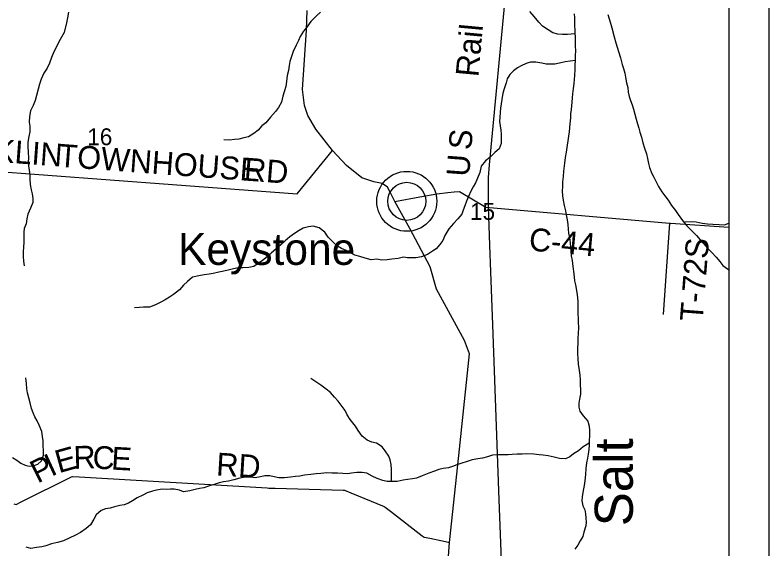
# Model space of a CAD drawing. Extents: x 0 to 34, y 0 to 22.
# Drawn here: x 7.127 to 9, y 16.276 to 17.601 of the extents above; entities that cross this region are included whole.
import ezdxf

# ---------------------------------------------------------------- set-up
doc = ezdxf.new("R2010")
doc.units = 0
for name, color, linetype in [('GM_X_County_Road', 7, 'Continuous'), ('GM_X_County_Road_Text', 7, 'Continuous'), ('GM_X_Major_River', 7, 'Continuous'), ('GM_X_Major_River_Text', 7, 'Continuous'), ('GM_X_Minor_River', 7, 'Continuous'), ('GM_X_Rail_Line', 7, 'Continuous'), ('GM_X_Rail_Line_Text', 7, 'Continuous'), ('GM_X_Section_Text', 7, 'Continuous'), ('GM_X_Township_Road', 7, 'Continuous'), ('GM_X_Township_Road_Text', 7, 'Continuous'), ('GM_X_Unincorporated', 7, 'Continuous'), ('GM_X_Unincorporated_Location', 7, 'Continuous'), ('GM_X_Unincorporated_Text', 7, 'Continuous'), ('SH_Data', 7, 'Continuous')]:
    doc.layers.add(name, color=color, linetype=linetype)

msp = doc.modelspace()

# ---------------------------------------------------------------- linework, layer by layer
at = {"layer": 'GM_X_County_Road'}
for points in [[(8.1931, 16.1084), (8.2061, 16.2922), (8.2296, 16.5078), (8.2558, 16.7601), (8.2439, 16.7934), (8.1745, 16.9209), (8.158, 16.9765), (8.108, 17.0711), (8.0705, 17.1387), (8.06, 17.1604), (8.0524, 17.174), (8.0395, 17.183), (8.0186, 17.1875), (7.9883, 17.1976), (7.9504, 17.2281), (7.9156, 17.2654), (7.8747, 17.318), (7.8541, 17.3516), (7.8465, 17.377), (7.841, 17.4164), (7.851, 17.564), (7.8526, 17.6125)], [(8.0705, 17.1387), (8.1327, 17.1497), (8.1746, 17.1571), (8.2019, 17.1607), (8.2181, 17.1623), (8.231, 17.1635), (8.2966, 17.1243), (8.7534, 17.085), (8.7553, 17.0848), (8.9, 17.0747)]]:
    msp.add_lwpolyline(points, dxfattribs=at)
at = {"layer": 'GM_X_Major_River'}
for points in [[(8.5163, 17.6046), (8.5166, 17.5948), (8.5172, 17.58), (8.5178, 17.5587), (8.5184, 17.5451), (8.5187, 17.5345), (8.519, 17.5246), (8.5192, 17.5121), (8.5188, 17.5015), (8.5183, 17.4897), (8.5182, 17.4768), (8.5177, 17.4662), (8.5168, 17.4515), (8.5151, 17.4318), (8.5135, 17.4189), (8.5123, 17.4056), (8.5114, 17.3962), (8.5102, 17.3852), (8.5085, 17.367), (8.5073, 17.3564), (8.5068, 17.3458), (8.5052, 17.3314), (8.5043, 17.3219), (8.5035, 17.3117), (8.5023, 17.3007), (8.5007, 17.289), (8.4991, 17.2787), (8.4959, 17.2606), (8.4942, 17.2481), (8.4919, 17.2337), (8.4898, 17.2136), (8.4885, 17.2007), (8.4873, 17.1871), (8.4868, 17.1753), (8.4863, 17.1647), (8.487, 17.1526), (8.4888, 17.1416), (8.4917, 17.1283), (8.4946, 17.1154), (8.4964, 17.1051), (8.4986, 17.093), (8.5007, 17.0816), (8.5014, 17.0702), (8.502, 17.0599), (8.5042, 17.0489), (8.506, 17.0356), (8.507, 17.0246), (8.5077, 17.0152), (8.5091, 17.0038), (8.5109, 16.9916), (8.513, 16.9768), (8.5151, 16.9586), (8.5173, 16.9419), (8.5191, 16.9316), (8.5212, 16.9221), (8.5234, 16.907), (8.5251, 16.891), (8.5254, 16.8804), (8.5253, 16.8705), (8.5256, 16.8588), (8.5259, 16.8485), (8.5262, 16.8387), (8.5268, 16.8254), (8.5263, 16.8106), (8.5251, 16.7993), (8.525, 16.7871), (8.5245, 16.7743), (8.5247, 16.7606), (8.525, 16.7488), (8.5264, 16.7344), (8.5285, 16.7189), (8.5299, 16.7075), (8.531, 16.6957)], [(8.531, 16.6957), (8.5312, 16.6832), (8.5319, 16.6707), (8.5318, 16.6601), (8.5298, 16.648), (8.5278, 16.6381), (8.5277, 16.6279), (8.5303, 16.618), (8.5385, 16.6065), (8.5501, 16.5928), (8.5538, 16.5806), (8.554, 16.57), (8.5543, 16.5575), (8.5538, 16.5439), (8.5533, 16.5332), (8.5525, 16.523), (8.5509, 16.5113), (8.5493, 16.501), (8.5469, 16.4897), (8.5453, 16.4757), (8.544, 16.4609), (8.5424, 16.4446), (8.5407, 16.4336), (8.5387, 16.4208), (8.5363, 16.4049), (8.5355, 16.395), (8.538, 16.3825), (8.5425, 16.3726), (8.5447, 16.3631), (8.5453, 16.3525), (8.5456, 16.3426), (8.5452, 16.3331), (8.5405, 16.3176), (8.5374, 16.307), (8.5308, 16.2957), (8.5255, 16.2852), (8.5174, 16.2754)]]:
    msp.add_lwpolyline(points, dxfattribs=at)
at = {"layer": 'GM_X_Minor_River'}
for points in [[(7.26, 17.6085), (7.2576, 17.5948), (7.2549, 17.5819), (7.249, 17.5583)], [(7.8862, 17.6083), (7.8764, 17.5992), (7.8623, 17.5853), (7.8517, 17.5713), (7.8441, 17.5614), (7.8357, 17.5478), (7.8311, 17.538), (7.8258, 17.527), (7.8181, 17.5108), (7.8128, 17.496), (7.8101, 17.4862), (7.8085, 17.4763), (7.8062, 17.4634), (7.8035, 17.4509), (7.8016, 17.4362), (7.7996, 17.424), (7.7958, 17.4108), (7.7927, 17.3998), (7.7889, 17.3854), (7.782, 17.3722), (7.774, 17.3616), (7.7619, 17.3476), (7.7501, 17.334), (7.7406, 17.3265), (7.7308, 17.3156), (7.7201, 17.3076), (7.7072, 17.299), (7.6959, 17.2968), (7.683, 17.293), (7.6725, 17.2927), (7.6596, 17.2905), (7.646, 17.2913)], [(8.5179, 17.5549), (8.4998, 17.5528), (8.4869, 17.5532), (8.4756, 17.5536), (8.4628, 17.5571), (8.4518, 17.5644), (8.4375, 17.5735), (8.4281, 17.5838), (8.4168, 17.5975), (8.4063, 17.6101)], [(8.6002, 17.6031), (8.6027, 17.5921), (8.6061, 17.5815), (8.6095, 17.5697), (8.6154, 17.5469), (8.6199, 17.5325), (8.6232, 17.5215), (8.6262, 17.5109), (8.6311, 17.4953), (8.6351, 17.4786), (8.6385, 17.4688), (8.6418, 17.457), (8.6433, 17.4475), (8.6463, 17.4335), (8.6493, 17.4213), (8.6507, 17.4103), (8.6529, 17.3993), (8.6563, 17.3891), (8.6604, 17.3781), (8.6638, 17.3678), (8.6667, 17.3553), (8.6705, 17.3428), (8.6734, 17.3314), (8.6768, 17.3204), (8.6794, 17.3109), (8.6835, 17.298), (8.6865, 17.2843), (8.6913, 17.2706), (8.6958, 17.2566), (8.698, 17.2456), (8.7006, 17.2327), (8.7036, 17.2232), (8.7088, 17.208), (8.7137, 17.1985), (8.7208, 17.1856), (8.7257, 17.1757), (8.7339, 17.1628), (8.7411, 17.1529), (8.7493, 17.1415), (8.7576, 17.1285), (8.7677, 17.116), (8.7749, 17.1061), (8.785, 17.0913), (8.7963, 17.078), (8.8095, 17.065), (8.82, 17.0543), (8.829, 17.0437), (8.8384, 17.033), (8.8475, 17.0228), (8.858, 17.0117), (8.8689, 16.9999), (8.8779, 16.9896), (8.8858, 16.9797), (8.8971, 16.971), (8.9, 16.9679)], [(7.249, 17.5583), (7.2358, 17.5349), (7.2305, 17.5228), (7.2236, 17.5099), (7.2175, 17.4963), (7.2129, 17.4819), (7.2068, 17.4698), (7.1988, 17.4569), (7.1916, 17.4425), (7.1878, 17.4297), (7.1847, 17.4176), (7.1801, 17.4013), (7.1774, 17.3895), (7.1721, 17.377), (7.1656, 17.3634), (7.1629, 17.3494), (7.1621, 17.3358), (7.1635, 17.3255), (7.1635, 17.3111), (7.1616, 17.3001), (7.1589, 17.2861), (7.1592, 17.2755), (7.1595, 17.2603), (7.1602, 17.2467), (7.1598, 17.2365), (7.1605, 17.227), (7.162, 17.2164), (7.1635, 17.2038), (7.1642, 17.1944), (7.1649, 17.1807), (7.1671, 17.1674), (7.1694, 17.1579), (7.1712, 17.1458), (7.1712, 17.1363), (7.1654, 17.1216), (7.159, 17.1072), (7.1566, 17.0951), (7.1551, 17.0833), (7.1494, 17.0716), (7.1486, 17.0621), (7.1493, 17.0481), (7.1492, 17.0386), (7.1481, 17.0246), (7.1473, 17.0144), (7.1476, 17.0019), (7.1483, 16.9905), (7.1494, 16.9787)], [(8.5183, 17.4886), (8.4938, 17.485), (8.4794, 17.482), (8.4681, 17.4794), (8.4567, 17.4791), (8.4469, 17.4795), (8.436, 17.4818), (8.4209, 17.4845), (8.4073, 17.4846), (8.397, 17.4808), (8.3849, 17.4752), (8.3751, 17.4703), (8.3652, 17.4632), (8.3561, 17.4534), (8.35, 17.4431), (8.3469, 17.4333), (8.342, 17.4182), (8.3393, 17.4076), (8.3362, 17.3917), (8.3346, 17.381), (8.3334, 17.3701), (8.331, 17.3371), (8.3325, 17.3265), (8.3336, 17.3159), (8.3347, 17.306), (8.335, 17.2927), (8.335, 17.2821), (8.33, 17.2689), (8.3194, 17.2602), (8.3068, 17.2474), (8.2955, 17.2394), (8.2848, 17.2262), (8.2814, 17.2103), (8.2764, 17.1963), (8.271, 17.1846), (8.2649, 17.1748), (8.2592, 17.1642), (8.2539, 17.1509), (8.2489, 17.1392), (8.2443, 17.1278), (8.2401, 17.1173), (8.2367, 17.1074), (8.2272, 17.0953), (8.2166, 17.084), (8.2044, 17.0708), (8.1949, 17.0542), (8.1899, 17.042), (8.1823, 17.0318), (8.1736, 17.0213), (8.1641, 17.0149), (8.152, 17.007), (8.1368, 17.001), (8.1232, 16.9984), (8.1126, 16.9984), (8.102, 16.9988), (8.0922, 17), (8.0786, 16.9971), (8.0631, 16.9952), (8.0514, 16.9934), (8.0385, 16.9931), (8.0257, 16.9954), (8.0117, 16.9936), (7.9966, 16.9978), (7.9838, 17.0017), (7.9713, 17.0051), (7.9604, 17.0112), (7.9498, 17.0166), (7.9381, 17.022), (7.9283, 17.0277), (7.9163, 17.0384), (7.9046, 17.0498), (7.8967, 17.062), (7.8824, 17.073), (7.8681, 17.0772), (7.856, 17.0754), (7.8431, 17.0721), (7.8332, 17.0664), (7.8215, 17.0589), (7.8101, 17.051), (7.798, 17.0408), (7.787, 17.031), (7.7756, 17.0212), (7.7631, 17.0102), (7.7532, 17.0012), (7.7418, 16.9921), (7.7308, 16.9846), (7.7206, 16.9775), (7.7081, 16.9749), (7.6926, 16.9742), (7.6813, 16.9738), (7.6695, 16.9709), (7.6567, 16.9679), (7.6457, 16.9653), (7.6332, 16.9631), (7.6196, 16.9597), (7.6094, 16.9579), (7.5969, 16.9564), (7.5841, 16.9542), (7.5678, 16.9505), (7.5556, 16.9399), (7.5458, 16.9305)], [(8.7877, 17.0881), (8.8092, 17.0889), (8.8194, 17.0881), (8.8341, 17.085), (8.8473, 17.083), (8.861, 17.0826), (8.8761, 17.0814), (8.8897, 17.0802), (8.9, 17.0847)], [(7.5458, 16.9305), (7.5355, 16.9192), (7.5204, 16.9079), (7.5105, 16.9007), (7.4999, 16.8943), (7.4893, 16.8887), (7.4764, 16.8823), (7.4609, 16.8763), (7.4461, 16.8764), (7.4363, 16.8753), (7.4235, 16.8742)], [(7.1208, 16.5027), (7.1314, 16.4959), (7.1415, 16.489), (7.1521, 16.4836), (7.1619, 16.4817), (7.1722, 16.4821), (7.1835, 16.4866), (7.193, 16.4945), (7.198, 16.5085), (7.1976, 16.518), (7.1973, 16.5343), (7.197, 16.5445), (7.1955, 16.5551), (7.1937, 16.5673), (7.1869, 16.5832), (7.182, 16.5942), (7.1764, 16.6041), (7.1719, 16.614), (7.1681, 16.6242), (7.1648, 16.6383), (7.1614, 16.6512), (7.1581, 16.6637), (7.1562, 16.6735), (7.1555, 16.6864), (7.154, 16.7008)], [(8.0621, 16.4434), (8.0623, 16.4607), (8.0624, 16.4732), (8.0616, 16.4854), (8.0594, 16.4968), (8.0557, 16.5062), (8.0467, 16.5196), (8.0388, 16.5291), (8.0252, 16.5382), (8.0131, 16.5409), (8.0018, 16.5459), (7.9894, 16.5562), (7.9792, 16.5703), (7.9729, 16.5805), (7.9593, 16.5969), (7.9522, 16.6091), (7.9473, 16.6193), (7.9372, 16.633), (7.9297, 16.6425), (7.9206, 16.6524), (7.9105, 16.6642), (7.9003, 16.6726), (7.8868, 16.6825), (7.8743, 16.6905), (7.8619, 16.6989)], [(8.5536, 16.5387), (8.5384, 16.5295), (8.5267, 16.5197), (8.5146, 16.5121), (8.5051, 16.5042), (8.4948, 16.4993), (8.4794, 16.5005), (8.4665, 16.504), (8.4518, 16.5067), (8.4393, 16.5087), (8.4295, 16.5095), (8.4159, 16.5114), (8.3989, 16.5119), (8.3868, 16.5108), (8.3743, 16.5112), (8.3622, 16.5102), (8.3524, 16.5098), (8.3278, 16.5099), (8.3135, 16.5089), (8.301, 16.5044), (8.2881, 16.501), (8.2771, 16.4999), (8.2631, 16.4973), (8.2476, 16.4925), (8.2374, 16.4891), (8.2245, 16.485), (8.2139, 16.4805), (8.2037, 16.4775), (8.1905, 16.4757), (8.1799, 16.4731), (8.1689, 16.4693), (8.1549, 16.4637), (8.1386, 16.457), (8.1246, 16.4513), (8.1148, 16.4499), (8.1023, 16.4484), (8.0913, 16.447), (8.0766, 16.4432), (8.0668, 16.4433), (8.0516, 16.4437), (8.0411, 16.4457), (8.0267, 16.451), (8.0143, 16.4568), (8.0007, 16.4637), (7.9894, 16.4656), (7.9765, 16.466), (7.9629, 16.4638), (7.9531, 16.4627), (7.9414, 16.4632), (7.9285, 16.4636), (7.9145, 16.4644), (7.9013, 16.4649), (7.8866, 16.4634), (7.8752, 16.4623), (7.862, 16.4609), (7.8465, 16.4591), (7.8348, 16.4568), (7.8238, 16.4557), (7.8117, 16.4539), (7.7969, 16.4528), (7.7822, 16.4525), (7.7705, 16.4552), (7.7603, 16.4572), (7.7475, 16.4576), (7.7372, 16.455), (7.7236, 16.4528), (7.7115, 16.454), (7.6987, 16.4537), (7.6854, 16.4514), (7.6707, 16.4473), (7.6578, 16.4444), (7.6446, 16.4422), (7.634, 16.4403), (7.6242, 16.4369), (7.6101, 16.4328), (7.5958, 16.428), (7.5856, 16.4257), (7.575, 16.4235), (7.561, 16.4202), (7.5455, 16.418), (7.5356, 16.4222), (7.5228, 16.4241), (7.513, 16.4246), (7.5024, 16.4238), (7.4922, 16.4239), (7.4786, 16.4217), (7.4684, 16.4195), (7.4555, 16.415), (7.4449, 16.4097), (7.4301, 16.4026), (7.4187, 16.3954), (7.4089, 16.3898), (7.3979, 16.3857), (7.3873, 16.3834), (7.3741, 16.3805), (7.3631, 16.3771), (7.3521, 16.3756), (7.3408, 16.3715), (7.3286, 16.3606), (7.3225, 16.3496), (7.3146, 16.336)], [(7.3146, 16.336), (7.3039, 16.3269), (7.2899, 16.3168), (7.277, 16.31), (7.2472, 16.2956)], [(7.2472, 16.2956), (7.2327, 16.2915), (7.218, 16.2882), (7.204, 16.2833), (7.1934, 16.2814), (7.1805, 16.2792), (7.1665, 16.277), (7.1548, 16.2805)]]:
    msp.add_lwpolyline(points, dxfattribs=at)
at = {"layer": 'GM_X_Rail_Line'}
msp.add_lwpolyline([(8.336, 16.2482), (8.3302, 16.398), (8.3141, 16.8322), (8.3089, 16.9635), (8.3066, 17.0299), (8.3031, 17.1252), (8.3035, 17.1977), (8.3057, 17.2297), (8.3479, 17.6756), (8.359, 17.7858), (8.3651, 17.8594), (8.3677, 17.925), (8.3681, 17.9495), (8.3622, 18.0352), (8.3594, 18.06), (8.3556, 18.089), (8.3502, 18.1187), (8.3464, 18.1394), (8.3312, 18.2048), (8.3106, 18.2737), (8.2615, 18.4057), (8.1892, 18.5986), (8.0513, 18.9649)], dxfattribs=at)
at = {"layer": 'GM_X_Township_Road'}
msp.add_line((8.7534, 17.085), (8.7373, 16.8583), dxfattribs=at)
for points in [[(6.5886, 17.2499), (7.8282, 17.1576), (7.9156, 17.2654)], [(7.1241, 16.3881), (7.1299, 16.3865), (7.1424, 16.3927), (7.2671, 16.4546), (7.2699, 16.456), (7.2867, 16.455), (7.7536, 16.4274), (7.7574, 16.4271), (7.7734, 16.4266), (7.9425, 16.4215), (7.9455, 16.4214), (7.9612, 16.415), (8.0441, 16.3811), (8.0468, 16.38), (8.0602, 16.3696), (8.1388, 16.3086), (8.1432, 16.3052), (8.1572, 16.3023), (8.1962, 16.2943), (8.2061, 16.2922)]]:
    msp.add_lwpolyline(points, dxfattribs=at)
at = {"layer": 'GM_X_Unincorporated'}
for radius in [0.0744, 0.0472]:
    msp.add_circle((8.1003, 17.1389), radius, dxfattribs=at)
at = {"layer": 'GM_X_Unincorporated_Location'}
msp.add_line((8.1003, 17.1389), (8.1003, 17.1389), dxfattribs=at)
at = {"layer": 'SH_Data'}
for p, q in [((9, 21), (9, 14)), ((8.9, 20.9), (8.9, 14.1))]:
    msp.add_line(p, q, dxfattribs=at)

# ---------------------------------------------------------------- texts
at = {"layer": 'GM_X_County_Road_Text'}
msp.add_text('C-44', height=0.05682, rotation=354.8369, dxfattribs=at).set_placement((8.4022, 17.017))
at = {"layer": 'GM_X_Major_River_Text'}
msp.add_text('Salt', height=0.09471, rotation=90.0001, dxfattribs=at).set_placement((8.6619, 16.3322))
at = {"layer": 'GM_X_Rail_Line_Text'}
for s, height, rotation, p in [('Rail', 0.05663, 84.7218, (8.2779, 17.4464)), ('S', 0.0566, 84.4602, (8.2601, 17.265)), ('U', 0.0566, 85.7149, (8.2552, 17.199))]:
    msp.add_text(s, height=height, rotation=rotation, dxfattribs=at).set_placement(p)
at = {"layer": 'GM_X_Section_Text'}
for s, p in [('16', (7.3065, 17.2783)), ('15', (8.2574, 17.0929))]:
    msp.add_text(s, height=0.04186, rotation=0, dxfattribs=at).set_placement(p)
at = {"layer": 'GM_X_Township_Road_Text'}
for s, height, rotation, p in [('FRANKLIN', 0.05682, 355.7789, (6.8678, 17.2526)), ('TOWNHOUSE', 0.05682, 355.732, (7.2336, 17.2251)), ('RD', 0.05682, 355.5623, (7.6945, 17.1909)), ('T-72S', 0.05682, 85.6016, (8.8354, 16.8394)), ('E', 0.0568, 15.6163, (7.2358, 16.4636)), ('R', 0.0568, 1.495, (7.2731, 16.4745)), ('C', 0.0568, 356.8018, (7.3185, 16.4757)), ('E', 0.0568, 356.7755, (7.3651, 16.4731)), ('P', 0.0568, 26.2909, (7.1829, 16.4378)), ('I', 0.0568, 24.8019, (7.2169, 16.4546)), ('RD', 0.05682, 356.5467, (7.6258, 16.4584))]:
    msp.add_text(s, height=height, rotation=rotation, dxfattribs=at).set_placement(p)
at = {"layer": 'GM_X_Unincorporated_Text'}
msp.add_text('Keystone', height=0.07898, rotation=0, dxfattribs=at).set_placement((7.532, 16.9811))

doc.saveas('drawing.dxf')
